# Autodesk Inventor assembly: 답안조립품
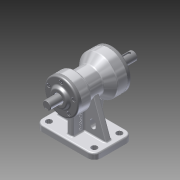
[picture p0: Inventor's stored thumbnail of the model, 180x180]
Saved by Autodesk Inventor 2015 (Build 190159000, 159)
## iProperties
Created: 2015-08
Part Number: 답안조립품
Document SubType Name: Assembly
Designer: 601
Author: 601
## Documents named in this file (10)
- C:\Users\601\Desktop\450806V1032\답안조립품.iam
- C:\Users\601\Desktop\450806V1032\M4x0.5.ipt
- C:\Users\601\Desktop\450806V1032\뒤커버.ipt
- C:\Users\601\Desktop\450806V1032\베어링 6203.ipt
- C:\Users\601\Desktop\450806V1032\베어링 6205.ipt
- C:\Users\601\Desktop\450806V1032\본체.ipt
- C:\Users\601\Desktop\450806V1032\앞커버.ipt
- C:\Users\601\Desktop\450806V1032\오일실 .ipt
- 오일실 .ipt
- C:\Users\601\Desktop\450806V1032\축.ipt
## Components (10 placed, 1 different names)
1. M4x0.5:1 — Insert:1
2. M4x0.5:2 — Insert:2
3. M4x0.5:3 — Mate:16
4. M4x0.5:4 — Mate:17
5. M4x0.5:5 — Mate:18
6. M4x0.5:6 — Mate:15
7. M4x0.5:7 — Mate:25, Mate:26
8. M4x0.5:8 — Mate:23, Mate:24
9. M4x0.5:9 — Mate:21, Mate:22
10. M4x0.5:10 — Mate:19, Mate:20
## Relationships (14: Mate 12, Insert 2)
- Insert:1: M4x0.5:1
- Insert:2: M4x0.5:2
- Mate:15: M4x0.5:6
- Mate:16: M4x0.5:3
- Mate:17: M4x0.5:4
- Mate:18: M4x0.5:5
- Mate:19: M4x0.5:10
- Mate:20: M4x0.5:10
- Mate:21: M4x0.5:9
- Mate:22: M4x0.5:9
- Mate:23: M4x0.5:8
- Mate:24: M4x0.5:8
- Mate:25: M4x0.5:7
- Mate:26: M4x0.5:7
